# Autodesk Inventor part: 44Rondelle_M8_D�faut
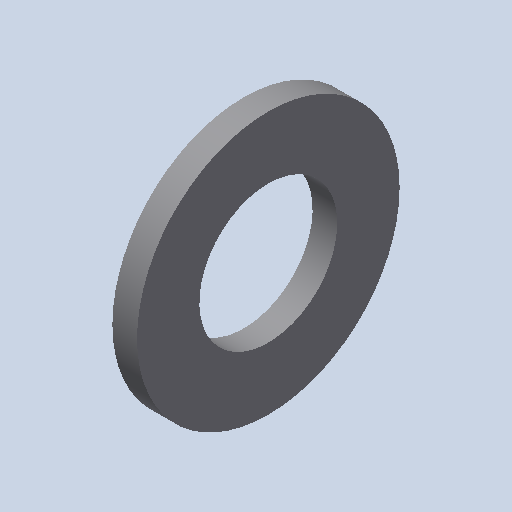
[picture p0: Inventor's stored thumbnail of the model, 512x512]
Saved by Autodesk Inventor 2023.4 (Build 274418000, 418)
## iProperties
Created: 2011-01
Part Number: 44Rondelle_M8_D�faut
Document SubType Name: Modeling
Designer: eric
Density: 1 g/cm^3
Mass: 0.218466 g
Surface Area: 4.06271 cm^2
Volume: 0.218466 cm^3
Material: Générique
Appearance: Par défaut
Author: eric
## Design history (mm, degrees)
feature "Base1"
node "Corps solides"
node "Corps surfaciques"
node "Solide1"
